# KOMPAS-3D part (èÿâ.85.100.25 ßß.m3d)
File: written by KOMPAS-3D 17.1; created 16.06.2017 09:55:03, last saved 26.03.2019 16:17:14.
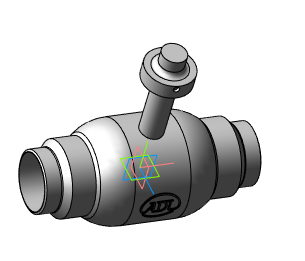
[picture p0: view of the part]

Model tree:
1. Операция без истории:2  (labels: Сталь 20  ГОСТ 1050-88)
